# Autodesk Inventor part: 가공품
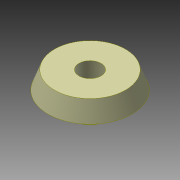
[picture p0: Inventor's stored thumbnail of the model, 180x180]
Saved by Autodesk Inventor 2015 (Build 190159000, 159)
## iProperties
Created: 2023-11
Part Number: 가공품
Material: 알루미늄 6061
Document SubType Name: Modeling
Designer: mdu-01
Density: 1 g/cm^3
Appearance: 기본값(1)
Author: mdu-01
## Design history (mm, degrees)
sketch "스케치1"
  geometry: L1 (0, 4)-(0, -4); L2 (0, 4)-(8.044, 4); L3 (8.044, 4)-(9.5, 0); L4 (9.5, 0)-(5, 0); L5 (5, 0)-(5, -3); L6 (4, -4)-(0, -4); L7 (5, -3)-(4, -4); 2 further points
  constraints: 14 end point, 3 point on line, 2 parallel, 2 perpendicular, 1 midpoint, 1 vertical
  dimensions: "d0" = 4 distance between parallel lines of L6 L4; "d3" = 1 distance of L5.end point (5, -4); "d4" = 1 distance of L6.start point (5, -4) (= d3); "d5" = 10 diameter of L5 L1; "d6" = 19 diameter of L3.end L1; "d7" = 8 distance between parallel lines of L6 L2; "d8" = 20 deg angle of L1 L3
revolve "회전1" sketch "스케치1" stored, may be unused: angle "d9" = 90 deg
hole "구멍1" diameter "d12" = 5; stored, may be unused: countersink angle "d16" = 90 deg, drill point angle "d18" = 118 deg; dims "d10" = 10, "d11" = 10, "d13" = 6, "d14" = 4, "d15" = 2, "d17" = 5
node "솔리드1"
